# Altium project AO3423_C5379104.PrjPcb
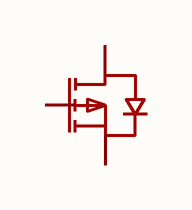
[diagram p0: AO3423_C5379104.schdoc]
1 sheet, 1 parts. Net scope: global (net labels, ports and power ports of the same name join across sheets).

## Sheet AO3423_C5379104.schdoc
size 127 x 101 mm

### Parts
Q?  ao3423_c5379104  [SOT-23-3_L2.9-W1.6-P1.90-LS2.8-BR]  (value not drawn)

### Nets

Not connected (* = marked no-connect by the designer): Q? 1(G) 2(S) 3(D)

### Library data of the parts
Q? = ao3423_c5379104: 数量:1个P沟道;漏源电压(Vdss):20V;连续漏极电流(Id):2A;导通电阻(RDS(on)):95mΩ@4.5V;耗散功率(Pd):1.56W;阈值电压(Vgs(th)):700mV;; Manufacturer: MSKSEMI(美森科); ManufacturerPart: AO3423; AddInBom: yes; ModelId: 89cb27a44ab2466697082bb9fd73a7d0; ModelName: SOT-23-3L_L2.9-W1.6-H1.1-LS2.8-P0.95; ModelTransform: 114.173,110.236,0,90,0,0,0,0,0; Number: 1个P沟道; Drain to Source Voltage: 20V; Current - Continuous Drain(Id): 2A; Pd - Power Dissipation: 1.56W; Gate Threshold Voltage (Vgs(th)): 700mV; Gate Charge(Qg): 3nC@4.5V; Input Capacitance(Ciss): 180pF; Reverse Transfer Capacitance (Crss@Vds): 25pF; Output Capacitance(Coss): 35pF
